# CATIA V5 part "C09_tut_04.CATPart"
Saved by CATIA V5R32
Part number: Part1
Bounding box of the stored display mesh (mm): x -112.5 to 112.5, y -202.31 to 80, z -202.31 to 85
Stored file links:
  D:\PROJECTS\Project 2022\CATIA V5 6R 2022\Resources\Tutorial Files\c09_catia_v5_6r2022_tut\C09_tut_04.CATPart
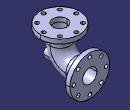
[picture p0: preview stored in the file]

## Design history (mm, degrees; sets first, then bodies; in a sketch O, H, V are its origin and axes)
Body1 (main body)
  Sketch1 on yz-plane, origin (0, 0, 0), H (0, 1, 0), V (0, 0, 1)
    line L1 (-90, 60) -> (-90, 0)
    point P1 (-90, 60)
    arc A1 centre (0, 0) radius 90 from (-90, 0) to (0, -90) ccw
    point P3 (0, 0)
    line L2 (0, -90) -> (55, -90)
    point P5 (55, -90)
    distance P1 L2 = 150
    distance P5 L1 = 145
    radius A1 = 90
    vertical: L1 V
    tangency: A1 L1, L2 A1
    horizontal: L2 H
    coincidence: P3 O
  Plane1: type Normal, Curve Sketch1, RefPoint Sketch1.P5, Ratio 0
  Sketch2 on Plane1, origin (0, 55, 0), H (-1, 0, 0), V (0, 0, 1)
    circle A1 centre (0, -90) radius 48.5
    point P1 (0, -90)
    reference projected point E1 (0, -90) from Sketch1.P5
    radius A1 = 48.5
    coincidence: P1 V, P1 E1
  Rib1: profile Sketch2, centre curve Sketch1, thin wall 16
  Sketch3 on face of Rib1, origin (0, 55, 0), H (-1, 0, 0), V (0, 0, 1)
    circle A1 centre (0, -90) radius 112.5
    point P1 (0, -90)
    reference projected circle E1 centre (0, -90) radius 56.5 from edge [face of Rib1 | face of Rib1]
    circle A2 centre (0, -90) radius 40.5
    reference projected circle E2 centre (0, -90) radius 40.5 from edge [face of Rib1 | face of Rib1]
    radius A1 = 112.5
    coincidence: P1 V, A2 E2
    concentricity: A1 E1
  Pad1: profile Sketch3, direction (0, 1, 0), length 25
  Sketch4 on face of Rib1, origin (0, 0, 60), H (1, 0, 0), V (0, 1, 0)
    circle A1 centre (0, -90) radius 112.5
    point P1 (0, -90)
    reference projected circle E1 centre (0, -90) radius 56.5 from edge [face of Rib1 | face of Rib1]
    circle A2 centre (0, -90) radius 40.5
    reference projected circle E2 centre (0, -90) radius 40.5 from edge [face of Rib1 | face of Rib1]
    radius A1 = 112.5
    coincidence: P1 V, A2 E2
    concentricity: A1 E1
  Pad2: profile Sketch4, direction (0, 0, 1), length 25
  Plane2: type Offset, RefPlane end face of Pad1, Offset 240
  Sketch5 on Plane2, origin (0, -160, 0), H (-1, 0, 0), V (0, 0, 1)
    circle A1 centre (0, -90) radius 25
    point P1 (0, -90)
    reference projected line E1 (-112.5, 85) -> (112.5, 85) from edge [face of Pad2 from Sketch4.A1 | end face of Pad2]
    radius A1 = 25
    distance E1 P1 = 175
    coincidence: P1 V
  Pad3: profile Sketch5, direction (0, 1, 0), up to the existing solid (limit type 2)
  Point1: type Center, Curve edge [start face of Pad3 | face of Pad3 from Sketch5.A1]
  Sketch6 on start face of Pad3, origin (0, -160, -90), H (1, 0, 0), V (0, 0, 1)
    point P1 (0, 0)
    reference projected point E1 (0, 0) from Point1
    coincidence: E1 P1
  Hole1: placed by Sketch6, at (0, -160, -90) direction (0, 1, 0), diameter 20, through (limit type 6), counterbore diameter 24, counterbore depth 28
  Sketch7 on end face of Pad1, origin (0, 80, 0), H (-1, 0, 0), V (0, 0, 1)
    construction circle A1 centre (0, -90) radius 92.5
    point P1 (0, -90)
    reference projected circle E1 centre (0, -90) radius 112.5 from edge [face of Pad1 from Sketch3.A1 | end face of Pad1]
    point P2 (0, 2.5)
    radius A1 = 92.5
    coincidence: P1 V, P2 A1, P2 V
    concentricity: A1 E1
  Sketch8 on end face of Pad1, origin (0, 80, 2.5), H (1, 0, 0), V (0, 0, -1)
    point P1 (0, 0)
    reference projected point E1 (0, 0) from Sketch7.P2
    coincidence: E1 P1
  Hole2: placed by Sketch8, at (0, 80, 2.5) direction (0, -1, 0), diameter 20.5, through (limit type 6)
  CircPattern1: of Hole2, instances 8, angular step 45 {= 360.0*1 deg/CircPattern1.AngularNumber}, axis from face of Pad1
  Sketch9 on end face of Pad2, origin (0, 0, 85), H (1, 0, 0), V (0, 1, 0)
    construction circle A1 centre (0, -90) radius 92.5
    point P1 (0, -90)
    reference projected circle E1 centre (0, -90) radius 112.5 from edge [face of Pad2 from Sketch4.A1 | end face of Pad2]
    point P2 (0, 2.5)
    radius A1 = 92.5
    coincidence: P1 V, P2 A1, P2 V
    concentricity: A1 E1
  Sketch10 on end face of Pad2, origin (0, 2.5, 85), H (1, 0, 0), V (0, 1, 0)
    point P1 (0, 0)
    reference projected point E1 (0, 0) from Sketch9.P2
    coincidence: E1 P1
  Hole3: placed by Sketch10, at (0, 2.5, 85) direction (0, 0, -1), diameter 20.5, through (limit type 6)
  CircPattern2: of Hole3, instances 8, angular step 45 {= 360.0*1 deg/CircPattern2.AngularNumber}, axis from face of Pad2 from Sketch4.A2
